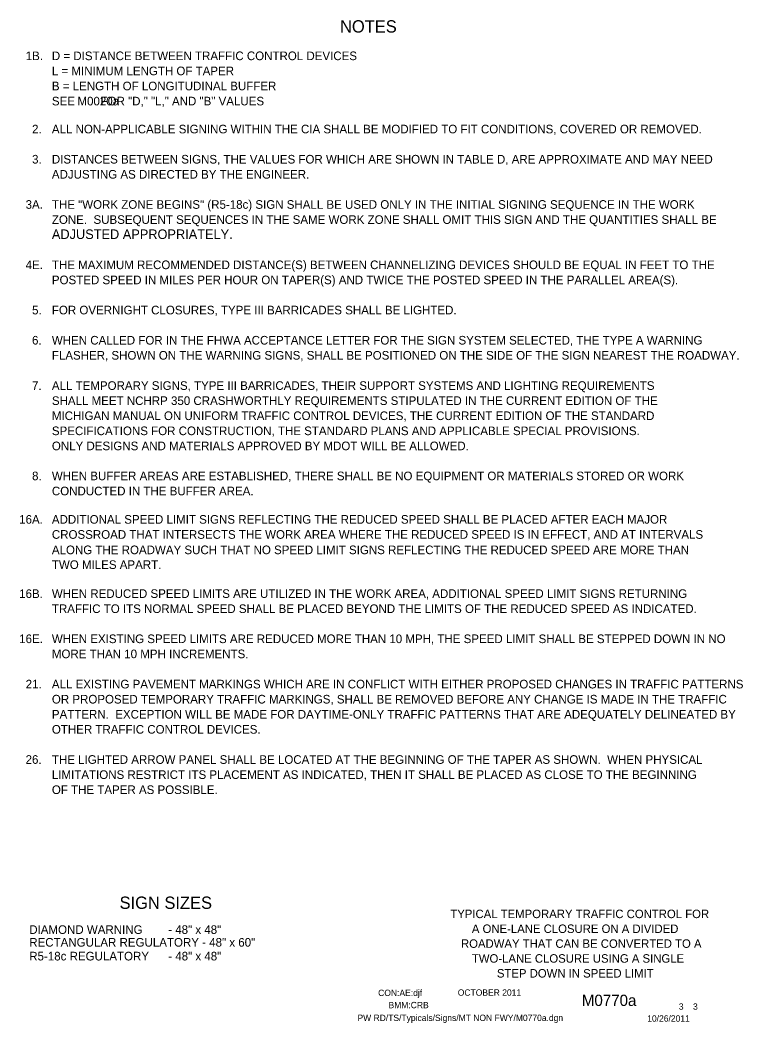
# Model space of a CAD drawing. Extents: x 16744 to 19504, y 5731 to 6974.
# Drawn here: x 18800 to 19504, y 5932 to 6909 of the extents above; entities that cross this region are included whole.
import ezdxf

# ---------------------------------------------------------------- set-up
doc = ezdxf.new("R2010")
doc.units = 0
for name, color, linetype in [('BORDER', 7, 'Continuous'), ('BORDER_SIGNAL_WO', 7, 'Continuous'), ('TYPICAL_TEXT_DIMEN_PR', 7, 'Continuous')]:
    doc.layers.add(name, color=color, linetype=linetype)

msp = doc.modelspace()

# ---------------------------------------------------------------- linework, layer by layer
at = {"layer": 'BORDER'}
msp.add_line((19347.25, 6011.25), (19347.25, 6011.25), dxfattribs=at)
msp.add_line((19347.25, 6011.25), (19347.25, 6011.25), dxfattribs=at)

# ---------------------------------------------------------------- texts
for s, p in [('TYPICAL TEMPORARY TRAFFIC CONTROL FOR', (19219.04, 6033.99)), ('A ONE-LANE CLOSURE ON A DIVIDED', (19240.02, 6019.51)), ('ROADWAY THAT CAN BE CONVERTED TO A', (19229.42, 6005.04)), ('TWO-LANE CLOSURE USING A SINGLE', (19240.06, 5990.56)), ('STEP DOWN IN SPEED LIMIT', (19264.42, 5976.08))]:
    msp.add_text(s, height=8.2598, dxfattribs=at).set_placement(p)
at = {"layer": 'BORDER_SIGNAL_WO'}
for s, height, p in [('CON:AE:djf', 6.2, (19148.69, 5958.06)), ('    OCTOBER 2011    ', 6.2, (19217.08, 5958.34)), ('BMM:CRB   ', 6.2, (19158.81, 5946.17)), ('    M0770a   ', 11, (19330.86, 5948.38)), (' 3    3 ', 6.2, (19439.45, 5944.7)), ('PW RD/TS/Typicals/Signs/MT NON FWY/M0770a.dgn    ', 6.2, (19128.55, 5933.71)), ('10/26/2011    ', 6.2, (19410.93, 5933.13))]:
    msp.add_text(s, height=height, dxfattribs=at).set_placement(p)
at = {"layer": 'TYPICAL_TEXT_DIMEN_PR'}
for s, height, p in [('NOTES', 12, (19111.55, 6897)), ('1B.', 8.4, (18805.19, 6870.11)), ('D = DISTANCE BETWEEN TRAFFIC CONTROL DEVICES', 8.4, (18830.7, 6870.11)), ('L = MINIMUM LENGTH OF TAPER', 8.4, (18830.7, 6855.41)), ('B = LENGTH OF LONGITUDINAL BUFFER', 8.4, (18830.7, 6840.71)), ('SEE        FOR "D," "L," AND "B" VALUES', 8.4, (18830.7, 6826.01)), ('M0020a', 8.4, (18855.62, 6826.01)), ('2.', 8.4, (18811.39, 6798.75)), ('ALL NON-APPLICABLE SIGNING WITHIN THE CIA SHALL BE MODIFIED TO FIT CONDITIONS, COVERED OR REMOVED.', 8.4, (18830.7, 6798.75)), ('3.', 8.4, (18811.39, 6769.35)), ('DISTANCES BETWEEN SIGNS, THE VALUES FOR WHICH ARE SHOWN IN TABLE D, ARE APPROXIMATE AND MAY NEED', 8.4, (18830.7, 6769.35)), ('ADJUSTING AS DIRECTED BY THE ENGINEER.', 8.4, (18830.7, 6754.65)), ('THE "WORK ZONE BEGINS" (R5-18c) SIGN SHALL BE USED ONLY IN THE INITIAL SIGNING SEQUENCE IN THE WORK', 8.4, (18830.7, 6725.25)), ('3A.', 8.4, (18805.09, 6725.25)), ('ZONE.  SUBSEQUENT SEQUENCES IN THE SAME WORK ZONE SHALL OMIT THIS SIGN AND THE QUANTITIES SHALL BE', 8.4, (18830.7, 6710.55)), ('ADJUSTED APPROPRIATELY.', 9.3, (18830.7, 6695.85)), ('THE MAXIMUM RECOMMENDED DISTANCE(S) BETWEEN CHANNELIZING DEVICES SHOULD BE EQUAL IN FEET TO THE', 8.4, (18830.7, 6666.45)), ('4E.', 8.4, (18805.13, 6666.45)), ('POSTED SPEED IN MILES PER HOUR ON TAPER(S) AND TWICE THE POSTED SPEED IN THE PARALLEL AREA(S).', 8.4, (18830.7, 6651.75)), ('5.', 8.4, (18811.39, 6622.35)), ('FOR OVERNIGHT CLOSURES, TYPE III BARRICADES SHALL BE LIGHTED.', 8.4, (18830.7, 6622.35)), ('6.', 8.4, (18811.34, 6592.95)), ('WHEN CALLED FOR IN THE FHWA ACCEPTANCE LETTER FOR THE SIGN SYSTEM SELECTED, THE TYPE A WARNING ', 8.4, (18830.7, 6592.95)), ('FLASHER, SHOWN ON THE WARNING SIGNS, SHALL BE POSITIONED ON THE SIDE OF THE SIGN NEAREST THE ROADWAY.', 8.4, (18830.7, 6578.25)), ('7.', 8.4, (18811.34, 6548.75)), ('ALL TEMPORARY SIGNS, TYPE III BARRICADES, THEIR SUPPORT SYSTEMS AND LIGHTING REQUIREMENTS', 8.4, (18830.7, 6548.77)), ('SHALL MEET NCHRP 350 CRASHWORTHLY REQUIREMENTS STIPULATED IN THE CURRENT EDITION OF THE', 8.4, (18830.7, 6534.07)), ('MICHIGAN MANUAL ON UNIFORM TRAFFIC CONTROL DEVICES, THE CURRENT EDITION OF THE STANDARD', 8.4, (18830.7, 6519.37)), ('SPECIFICATIONS FOR CONSTRUCTION, THE STANDARD PLANS AND APPLICABLE SPECIAL PROVISIONS.', 8.4, (18830.7, 6504.67)), ('ONLY DESIGNS AND MATERIALS APPROVED BY MDOT WILL BE ALLOWED.', 8.4, (18830.7, 6489.97)), ('8.', 8.4, (18811.39, 6460.72)), ('WHEN BUFFER AREAS ARE ESTABLISHED, THERE SHALL BE NO EQUIPMENT OR MATERIALS STORED OR WORK     ', 8.4, (18830.7, 6460.72)), ('CONDUCTED IN THE BUFFER AREA.', 8.4, (18830.7, 6446.02)), ('16A.', 8.4, (18798.83, 6418.37)), ('ADDITIONAL SPEED LIMIT SIGNS REFLECTING THE REDUCED SPEED SHALL BE PLACED AFTER EACH MAJOR', 8.4, (18830.7, 6418.37)), ('CROSSROAD THAT INTERSECTS THE WORK AREA WHERE THE REDUCED SPEED IS IN EFFECT, AND AT INTERVALS', 8.4, (18830.7, 6403.67)), ('ALONG THE ROADWAY SUCH THAT NO SPEED LIMIT SIGNS REFLECTING THE REDUCED SPEED ARE MORE THAN', 8.4, (18830.7, 6388.67)), ('TWO MILES APART.', 8.4, (18830.7, 6374.27)), ('16B.', 8.4, (18798.83, 6345.98)), ('WHEN REDUCED SPEED LIMITS ARE UTILIZED IN THE WORK AREA, ADDITIONAL SPEED LIMIT SIGNS RETURNING', 8.4, (18830.7, 6346.03)), ('TRAFFIC TO ITS NORMAL SPEED SHALL BE PLACED BEYOND THE LIMITS OF THE REDUCED SPEED AS INDICATED.', 8.4, (18830.7, 6331.33)), ('16E.', 8.4, (18798.84, 6302)), ('WHEN EXISTING SPEED LIMITS ARE REDUCED MORE THAN 10 MPH, THE SPEED LIMIT SHALL BE STEPPED DOWN IN NO', 8.4, (18830.7, 6302)), ('MORE THAN 10 MPH INCREMENTS.', 8.4, (18830.7, 6287.3)), ('21.', 8.4, (18805.14, 6257.84)), ('ALL EXISTING PAVEMENT MARKINGS WHICH ARE IN CONFLICT WITH EITHER PROPOSED CHANGES IN TRAFFIC PATTERNS', 8.4, (18830.7, 6257.84)), ('OR PROPOSED TEMPORARY TRAFFIC MARKINGS, SHALL BE REMOVED BEFORE ANY CHANGE IS MADE IN THE TRAFFIC', 8.4, (18830.7, 6243.14)), ('PATTERN.  EXCEPTION WILL BE MADE FOR DAYTIME-ONLY TRAFFIC PATTERNS THAT ARE ADEQUATELY DELINEATED BY', 8.4, (18830.7, 6228.44)), ('OTHER TRAFFIC CONTROL DEVICES.', 8.4, (18830.7, 6213.74)), ('26.', 8.4, (18805.09, 6184.34)), ('THE LIGHTED ARROW PANEL SHALL BE LOCATED AT THE BEGINNING OF THE TAPER AS SHOWN.  WHEN PHYSICAL', 8.4, (18830.7, 6184.34)), ('LIMITATIONS RESTRICT ITS PLACEMENT AS INDICATED, THEN IT SHALL BE PLACED AS CLOSE TO THE BEGINNING', 8.4, (18830.7, 6169.64)), ('OF THE TAPER AS POSSIBLE.', 8.4, (18830.7, 6154.94)), ('SIGN SIZES', 12, (18896.69, 6043)), ('DIAMOND WARNING        - 48" x 48"', 8.4, (18808.65, 6018.6)), ('RECTANGULAR REGULATORY - 48" x 60"', 8.4, (18808.65, 6006.2)), ('R5-18c REGULATORY      - 48" x 48"', 8.4, (18808.65, 5992.75))]:
    msp.add_text(s, height=height, dxfattribs=at).set_placement(p)

doc.saveas('drawing.dxf')
